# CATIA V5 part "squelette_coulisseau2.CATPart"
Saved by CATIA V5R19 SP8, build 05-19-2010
Part number: squelette_coulisseau2
Publications: "Plan.1", "Droite.1"
Bounding box of the stored display mesh (mm): x 0 to 0, y -28 to 0, z 0 to 8
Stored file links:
  C:\Users\ThinkMotion\Desktop\EU_thinkMotion\iao\IAO_MMS_Groupe3\pmayet\pmayet_avant_optimisation\pmayet_avant_optimisation\squelette_coulisseau2.CATPart
  C:\Users\ThinkMotion\Desktop\EU_thinkMotion\iao\IAO_MMS_Groupe3\pmayet\pmayet_avant_optimisation\pmayet_avant_optimisation\squelette.CATProduct
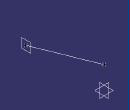
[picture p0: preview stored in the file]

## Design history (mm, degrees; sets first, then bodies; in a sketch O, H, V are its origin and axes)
Set1
  Point1 "Point2": linked copy from another document
  Point2 "Pointa": linked copy from another document
Set2
  Plane1: type OffsetPt, RefPlane yz-plane, RefPoint Point1
  Line1: type PtPt, FirstPoint Point1, SecondPoint Point2
Body1 (main body)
